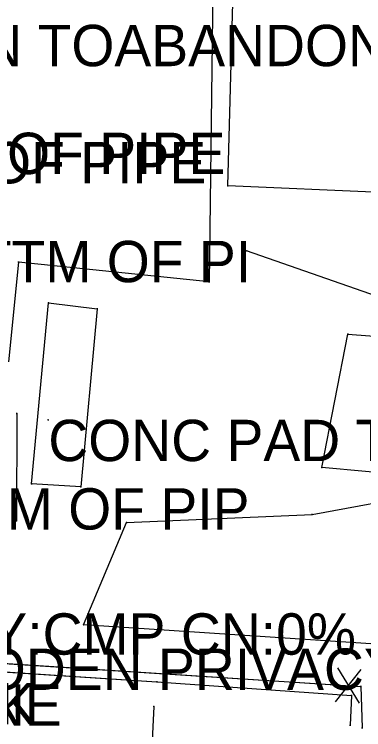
# Model space of a CAD drawing. Extents: x -99999 to 591807, y -99999 to 347168.
# Drawn here: x 591319 to 591361.2, y 320729.1 to 320815.7 of the extents above; entities that cross this region are included whole.
import ezdxf

# ---------------------------------------------------------------- set-up
doc = ezdxf.new("R2010")
doc.units = 0
for name, color, linetype in [('S_BREAKLINE', 7, 'Continuous'), ('S_BUILDING', 7, 'Continuous'), ('S_EDGE_CONCRETE', 7, 'Continuous'), ('S_ELECTRIC_UTILITIES_ANNOT', 7, 'Continuous'), ('S_FENCE', 7, 'Continuous'), ('S_FENCE_ANNOT', 7, 'Continuous'), ('S_GRD_PT_SYM', 7, 'Continuous'), ('S_MSC_PT_SYM', 7, 'Continuous'), ('S_PARKING', 7, 'Continuous'), ('S_RDW_PT_SYM', 7, 'Continuous'), ('S_SECONDARY_CTL_ANNOT', 7, 'Continuous'), ('S_SIDE_DRAIN_ANNOT', 7, 'Continuous'), ('S_STR_PT_SYM', 7, 'Continuous'), ('S_SURVEY_TEXT_ANNOT', 7, 'Continuous')]:
    doc.layers.add(name, color=color, linetype=linetype)

msp = doc.modelspace()

# ---------------------------------------------------------------- linework, layer by layer
at = {"layer": 'S_BREAKLINE'}
for points in [[(591348.942, 320872.286), (591351.427, 320825.484), (591343.005, 320821.997), (591342.497, 320783.289), (591319.45, 320785.697), (591318.243, 320773.636)], [(591395.379, 320868.429), (591389.934, 320793.678), (591379.152, 320738.403), (591327.316, 320741.827), (591332.52, 320754.181), (591354.945, 320755.151), (591368.943, 320757.756), (591370.738, 320778.808), (591347.042, 320787.061)], [(591319.242, 320767.377), (591319.203, 320754.389)], [(591335.82, 320731.949), (591334.2, 320699.184), (591332.329, 320664.008)]]:
    msp.add_lwpolyline(points, dxfattribs=at)
at = {"layer": 'S_BUILDING'}
for p, q in [((591344.776, 320794.918), (591345.373, 320817.041)), ((591375.807, 320793.55), (591344.776, 320794.918))]:
    msp.add_line(p, q, dxfattribs=at)
at = {"layer": 'S_EDGE_CONCRETE'}
for points in [[(591326.992, 320758.516), (591321.05, 320758.871), (591323.09, 320780.755), (591328.984, 320780.039), (591326.992, 320758.516)], [(591359.286, 320776.954), (591367.79, 320776.313), (591366.696, 320759.873), (591356.141, 320760.855), (591359.286, 320776.954)]]:
    msp.add_lwpolyline(points, dxfattribs=at)
for points in [[(591326.992, 320758.516), (591321.05, 320758.871), (591323.09, 320780.755), (591328.984, 320780.039)], [(591359.286, 320776.954), (591367.79, 320776.313), (591366.696, 320759.873), (591356.141, 320760.855)]]:
    msp.add_lwpolyline(points, close=True, dxfattribs=at)
at = {"layer": 'S_FENCE'}
for p, q in [((591289.889, 320738.946), (591360.836, 320734.377)), ((591357.764, 320732.523), (591360.889, 320736.426)), ((591358.027, 320736.61), (591360.626, 320732.339)), ((591360.836, 320734.377), (591361.017, 320729.341))]:
    msp.add_line(p, q, dxfattribs=at)
for points in [[(591315.139, 320737.32), (591357.223, 320734.61)], [(591360.836, 320734.377), (591361.017, 320729.341)]]:
    msp.add_lwpolyline(points, dxfattribs=at)
at = {"layer": 'S_GRD_PT_SYM'}
for points in [[(591347.042, 320787.061), (591347.026, 320787.014), (591347.042, 320787.061), (591347.09, 320787.045), (591347.042, 320787.061), (591347.059, 320787.108), (591347.042, 320787.061), (591346.995, 320787.077)], [(591319.45, 320785.697), (591319.499, 320785.692), (591319.45, 320785.697), (591319.455, 320785.747), (591319.45, 320785.697), (591319.4, 320785.702), (591319.45, 320785.697), (591319.445, 320785.647)], [(591342.497, 320783.289), (591342.492, 320783.239), (591342.497, 320783.289), (591342.547, 320783.284), (591342.497, 320783.289), (591342.502, 320783.339), (591342.497, 320783.289), (591342.447, 320783.294)], [(591319.242, 320767.377), (591319.292, 320767.377), (591319.242, 320767.377), (591319.242, 320767.427), (591319.242, 320767.377), (591319.192, 320767.377), (591319.242, 320767.377), (591319.241, 320767.327)], [(591354.945, 320755.151), (591354.936, 320755.2), (591354.945, 320755.151), (591354.896, 320755.142), (591354.945, 320755.151), (591354.954, 320755.102), (591354.945, 320755.151), (591354.994, 320755.16)], [(591319.203, 320754.389), (591319.253, 320754.389), (591319.203, 320754.389), (591319.203, 320754.439), (591319.203, 320754.389), (591319.153, 320754.389), (591319.203, 320754.389), (591319.202, 320754.339)], [(591332.52, 320754.181), (591332.518, 320754.231), (591332.52, 320754.181), (591332.471, 320754.179), (591332.52, 320754.181), (591332.523, 320754.131), (591332.52, 320754.181), (591332.57, 320754.183)], [(591327.316, 320741.827), (591327.27, 320741.846), (591327.316, 320741.827), (591327.297, 320741.781), (591327.316, 320741.827), (591327.362, 320741.807), (591327.316, 320741.827), (591327.336, 320741.873)], [(591335.82, 320731.949), (591335.87, 320731.947), (591335.82, 320731.949), (591335.822, 320731.999), (591335.82, 320731.949), (591335.77, 320731.952), (591335.82, 320731.949), (591335.817, 320731.899)]]:
    msp.add_lwpolyline(points, close=True, dxfattribs=at)
at = {"layer": 'S_MSC_PT_SYM'}
for points in [[(591323.062, 320766.618), (591323.062, 320766.668), (591323.062, 320766.618), (591323.012, 320766.618), (591323.062, 320766.618), (591323.062, 320766.568), (591323.062, 320766.618), (591323.112, 320766.618)], [(591360.836, 320734.377), (591360.836, 320734.427), (591360.836, 320734.377), (591360.785, 320734.377), (591360.836, 320734.377), (591360.836, 320734.327), (591360.836, 320734.377), (591360.886, 320734.377)], [(591361.017, 320729.341), (591361.017, 320729.391), (591361.017, 320729.341), (591360.967, 320729.341), (591361.017, 320729.341), (591361.017, 320729.291), (591361.017, 320729.341), (591361.068, 320729.341)]]:
    msp.add_lwpolyline(points, dxfattribs=at)
for points in [[(591336.2, 320734.918), (591336.203, 320734.968), (591336.2, 320734.918), (591336.15, 320734.922), (591336.2, 320734.918), (591336.196, 320734.869), (591336.2, 320734.918), (591336.25, 320734.915)], [(591359.735, 320733.284), (591359.785, 320733.282), (591359.735, 320733.284), (591359.738, 320733.334), (591359.735, 320733.284), (591359.685, 320733.287), (591359.735, 320733.284), (591359.733, 320733.234)], [(591359.566, 320729.662), (591359.616, 320729.66), (591359.566, 320729.662), (591359.569, 320729.712), (591359.566, 320729.662), (591359.516, 320729.664), (591359.566, 320729.662), (591359.564, 320729.612)]]:
    msp.add_lwpolyline(points, close=True, dxfattribs=at)
at = {"layer": 'S_PARKING'}
for points in [[(591289.568, 320737.964), (591336.2, 320734.918), (591359.735, 320733.284), (591359.566, 320729.662)], [(591289.568, 320737.964), (591312.884, 320736.441), (591336.2, 320734.918), (591359.735, 320733.284), (591359.566, 320729.662)]]:
    msp.add_lwpolyline(points, dxfattribs=at)
at = {"layer": 'S_RDW_PT_SYM'}
for points in [[(591323.09, 320780.755), (591323.09, 320780.805), (591323.09, 320780.755), (591323.04, 320780.755), (591323.09, 320780.755), (591323.09, 320780.705), (591323.09, 320780.755), (591323.14, 320780.755)], [(591323.09, 320780.755), (591323.096, 320780.804), (591323.09, 320780.755), (591323.04, 320780.761), (591323.09, 320780.755), (591323.084, 320780.705), (591323.09, 320780.755), (591323.139, 320780.749)], [(591328.984, 320780.039), (591328.984, 320780.089), (591328.984, 320780.039), (591328.934, 320780.039), (591328.984, 320780.039), (591328.984, 320779.989), (591328.984, 320780.039), (591329.034, 320780.039)], [(591328.984, 320780.039), (591329.034, 320780.034), (591328.984, 320780.039), (591328.989, 320780.088), (591328.984, 320780.039), (591328.935, 320780.043), (591328.984, 320780.039), (591328.98, 320779.989)], [(591359.286, 320776.954), (591359.286, 320777.004), (591359.286, 320776.954), (591359.236, 320776.954), (591359.286, 320776.954), (591359.286, 320776.904), (591359.286, 320776.954), (591359.336, 320776.954)], [(591359.286, 320776.954), (591359.29, 320777.004), (591359.286, 320776.954), (591359.237, 320776.958), (591359.286, 320776.954), (591359.283, 320776.904), (591359.286, 320776.954), (591359.336, 320776.951)], [(591359.286, 320776.954), (591359.237, 320776.964), (591359.286, 320776.954), (591359.277, 320776.905), (591359.286, 320776.954), (591359.335, 320776.945), (591359.286, 320776.954), (591359.296, 320777.003)], [(591356.141, 320760.855), (591356.141, 320760.905), (591356.141, 320760.855), (591356.091, 320760.855), (591356.141, 320760.855), (591356.141, 320760.805), (591356.141, 320760.855), (591356.191, 320760.855)], [(591356.141, 320760.855), (591356.092, 320760.865), (591356.141, 320760.855), (591356.132, 320760.806), (591356.141, 320760.855), (591356.19, 320760.846), (591356.141, 320760.855), (591356.151, 320760.904)], [(591321.05, 320758.871), (591321.05, 320758.921), (591321.05, 320758.871), (591321, 320758.871), (591321.05, 320758.871), (591321.05, 320758.821), (591321.05, 320758.871), (591321.1, 320758.871)], [(591321.05, 320758.871), (591321, 320758.876), (591321.05, 320758.871), (591321.045, 320758.821), (591321.05, 320758.871), (591321.099, 320758.866), (591321.05, 320758.871), (591321.054, 320758.921)], [(591326.992, 320758.516), (591326.992, 320758.566), (591326.992, 320758.516), (591326.942, 320758.516), (591326.992, 320758.516), (591326.992, 320758.466), (591326.992, 320758.516), (591327.042, 320758.516)], [(591326.992, 320758.516), (591326.989, 320758.466), (591326.992, 320758.516), (591327.042, 320758.513), (591326.992, 320758.516), (591326.995, 320758.566), (591326.992, 320758.516), (591326.942, 320758.519)], [(591326.992, 320758.516), (591327.042, 320758.511), (591326.992, 320758.516), (591326.997, 320758.566), (591326.992, 320758.516), (591326.942, 320758.521), (591326.992, 320758.516), (591326.987, 320758.466)]]:
    msp.add_lwpolyline(points, close=True, dxfattribs=at)
at = {"layer": 'S_STR_PT_SYM'}
msp.add_lwpolyline([(591344.776, 320794.918), (591344.776, 320794.968), (591344.776, 320794.918), (591344.726, 320794.918), (591344.776, 320794.918), (591344.776, 320794.868), (591344.776, 320794.918), (591344.826, 320794.918)], dxfattribs=at)

# ---------------------------------------------------------------- texts
at = {"layer": 'S_ELECTRIC_UTILITIES_ANNOT'}
msp.add_text('LOWEST UTILITY LINE', height=5, dxfattribs=at).set_placement((591252.976, 320729.605))
at = {"layer": 'S_FENCE_ANNOT'}
msp.add_text('6FT WOODEN PRIVACY FENCE CN:GOO', height=5, dxfattribs=at).set_placement((591289.889, 320733.946))
at = {"layer": 'S_SECONDARY_CTL_ANNOT'}
msp.add_text('PD:8 SPK', height=5, dxfattribs=at).set_placement((591291.431, 320729.796))
at = {"layer": 'S_SIDE_DRAIN_ANNOT'}
for s, p in [('CN:0% BTTM OF PIPE', (591274.993, 320796.341)), ('CN:%FILL CN:15% BTTM OF PIPE', (591236.271, 320795.212)), ('DI:18" TY:CMP CN:50% BTTM OF PI', (591235.99, 320783.257)), ('DI:18" TY:CMP CN:5% BTTM OF PIP', (591235.051, 320753.339)), ('DI:16" DI:18" TY:CMP CN:0% BTTM', (591271.545, 320738.209))]:
    msp.add_text(s, height=5, dxfattribs=at).set_placement(p)
at = {"layer": 'S_SURVEY_TEXT_ANNOT'}
for s, p in [(' ASPH APRON TOABANDON DW', (591274.212, 320809.387)), ('CONC PAD TO BURNT HOUSE', (591323.062, 320761.618))]:
    msp.add_text(s, height=5, dxfattribs=at).set_placement(p)

doc.saveas('drawing.dxf')
